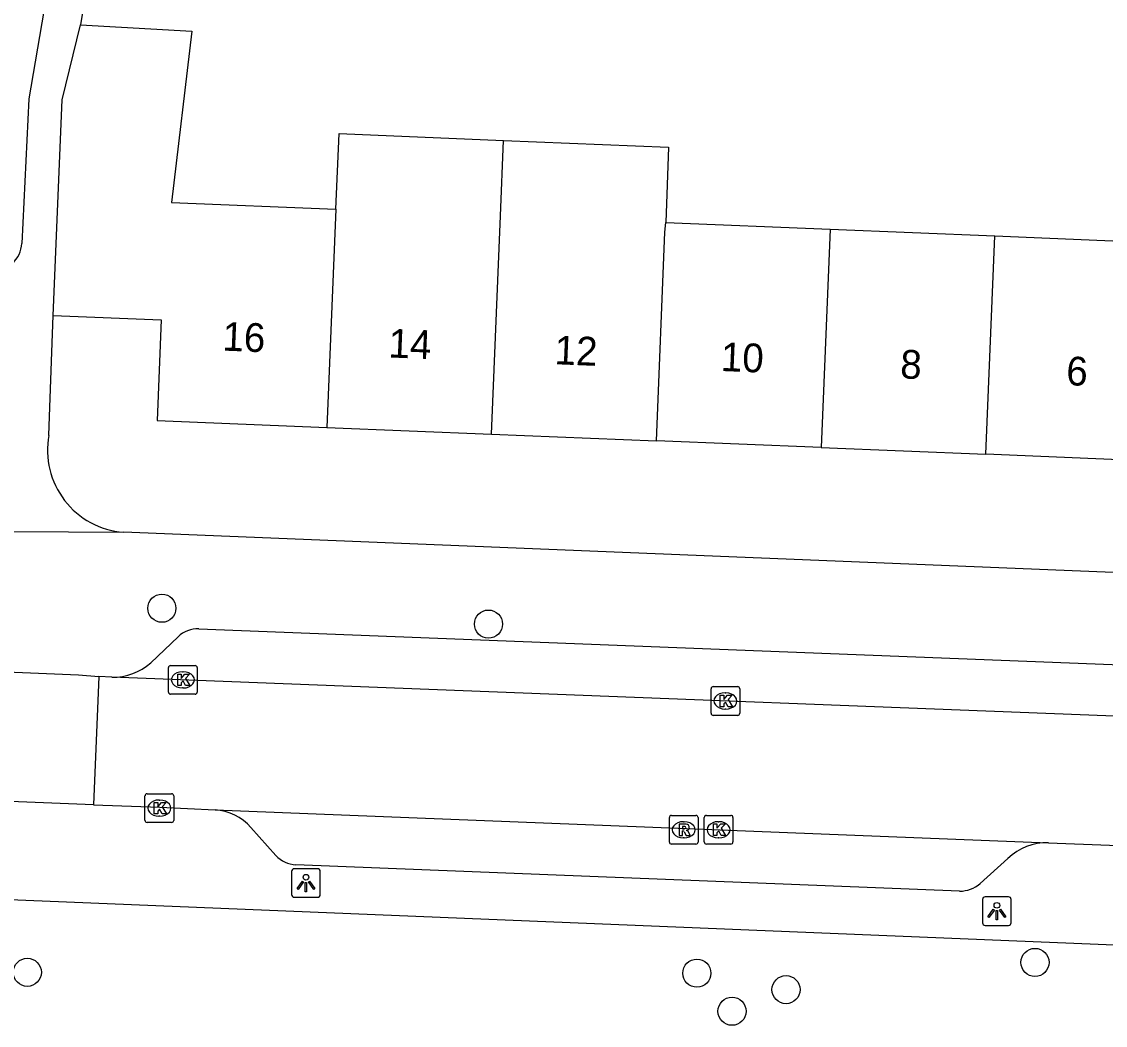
# Model space of a CAD drawing. Extents: x 159822 to 160765, y 380693 to 381634.
# Drawn here: x 160115.31 to 160153.02, y 380859.42 to 380894.34 of the extents above; entities that cross this region are included whole.
import ezdxf

# ---------------------------------------------------------------- set-up
doc = ezdxf.new("R2010")
doc.units = 0
for name, color, linetype in [('IMGEO_Boom', 7, 'Continuous'), ('IMGEO_Kolk', 7, 'Continuous'), ('IMGEO_Lichtpunt', 7, 'Continuous'), ('IMGEO_Muur', 7, 'Continuous'), ('IMGEO_Pand', 7, 'Continuous'), ('IMGEO_Pand_nummerreeks', 7, 'Continuous'), ('IMGEO_Rijbaan_lokaal_open', 7, 'Continuous'), ('IMGEO_Rioolput', 7, 'Continuous'), ('IMGEO_Voetpad_open', 7, 'Continuous')]:
    doc.layers.add(name, color=color, linetype=linetype)

msp = doc.modelspace()

# ---------------------------------------------------------------- linework, layer by layer
at = {"layer": 'IMGEO_Boom'}
for centre in [(160120.189, 380873.93), (160131.553, 380873.379), (160150.568, 380861.607), (160115.507, 380861.264), (160138.803, 380861.233), (160141.906, 380860.66), (160140.028, 380859.908)]:
    msp.add_circle(centre, 0.489, dxfattribs=at)
at = {"layer": 'IMGEO_Kolk'}
for p, q in [((160120.418, 380871.011), (160120.418, 380871.863)), ((160120.493, 380871.937), (160121.345, 380871.937)), ((160121.419, 380871.863), (160121.419, 380871.011)), ((160120.906, 380871.717), (160120.931, 380871.717)), ((160120.929, 380871.157), (160120.904, 380871.157)), ((160139.297, 380870.278), (160139.297, 380871.13)), ((160139.372, 380871.204), (160140.224, 380871.204)), ((160140.298, 380871.13), (160140.298, 380870.278)), ((160121.345, 380870.937), (160120.493, 380870.937)), ((160139.785, 380870.984), (160139.81, 380870.984)), ((160139.808, 380870.424), (160139.783, 380870.424)), ((160140.224, 380870.204), (160139.372, 380870.204)), ((160119.602, 380866.551), (160119.602, 380867.403)), ((160119.677, 380867.477), (160120.529, 380867.477)), ((160120.603, 380867.403), (160120.603, 380866.551)), ((160120.09, 380867.257), (160120.115, 380867.257)), ((160120.113, 380866.697), (160120.088, 380866.697)), ((160139.059, 380865.798), (160139.059, 380866.65)), ((160139.134, 380866.724), (160139.986, 380866.724)), ((160140.06, 380866.65), (160140.06, 380865.798)), ((160120.529, 380866.477), (160119.677, 380866.477)), ((160139.547, 380866.504), (160139.572, 380866.504)), ((160139.57, 380865.944), (160139.545, 380865.944)), ((160139.986, 380865.724), (160139.134, 380865.724))]:
    msp.add_line(p, q, dxfattribs=at)
for points in [[(160120.418, 380871.011), (160120.418, 380871.863)], [(160120.493, 380871.937), (160121.345, 380871.937)], [(160121.419, 380871.863), (160121.419, 380871.011)], [(160120.739, 380871.637), (160120.862, 380871.637), (160120.862, 380871.486), (160120.992, 380871.637), (160121.156, 380871.637), (160121.01, 380871.486), (160121.163, 380871.237), (160121.011, 380871.237), (160120.926, 380871.401), (160120.862, 380871.334), (160120.862, 380871.237), (160120.739, 380871.237), (160120.739, 380871.637)], [(160139.297, 380870.278), (160139.297, 380871.13)], [(160139.372, 380871.204), (160140.224, 380871.204)], [(160140.298, 380871.13), (160140.298, 380870.278)], [(160121.345, 380870.937), (160120.493, 380870.937)], [(160139.618, 380870.904), (160139.741, 380870.904), (160139.741, 380870.753), (160139.871, 380870.904), (160140.035, 380870.904), (160139.889, 380870.753), (160140.042, 380870.504), (160139.89, 380870.504), (160139.805, 380870.668), (160139.741, 380870.601), (160139.741, 380870.504), (160139.618, 380870.504), (160139.618, 380870.904)], [(160140.224, 380870.204), (160139.372, 380870.204)], [(160119.602, 380866.551), (160119.602, 380867.403)], [(160119.677, 380867.477), (160120.529, 380867.477)], [(160120.603, 380867.403), (160120.603, 380866.551)], [(160119.923, 380867.177), (160120.046, 380867.177), (160120.046, 380867.026), (160120.176, 380867.177), (160120.34, 380867.177), (160120.194, 380867.026), (160120.347, 380866.777), (160120.195, 380866.777), (160120.11, 380866.941), (160120.046, 380866.874), (160120.046, 380866.777), (160119.923, 380866.777), (160119.923, 380867.177)], [(160139.059, 380865.798), (160139.059, 380866.65)], [(160139.134, 380866.724), (160139.986, 380866.724)], [(160140.06, 380866.65), (160140.06, 380865.798)], [(160120.529, 380866.477), (160119.677, 380866.477)], [(160139.38, 380866.424), (160139.503, 380866.424), (160139.503, 380866.273), (160139.633, 380866.424), (160139.797, 380866.424), (160139.651, 380866.273), (160139.804, 380866.024), (160139.652, 380866.024), (160139.567, 380866.188), (160139.503, 380866.121), (160139.503, 380866.024), (160139.38, 380866.024), (160139.38, 380866.424)], [(160139.986, 380865.724), (160139.134, 380865.724)]]:
    msp.add_lwpolyline(points, dxfattribs=at)
for centre, start, end in [((160120.495, 380871.861), 91.552, 178.448), ((160120.495, 380871.861), 91.552, 178.448), ((160121.343, 380871.861), 1.552, 88.448), ((160121.343, 380871.861), 1.552, 88.448), ((160139.374, 380871.128), 91.552, 178.448), ((160139.374, 380871.128), 91.552, 178.448), ((160140.222, 380871.128), 1.552, 88.448), ((160140.222, 380871.128), 1.552, 88.448), ((160120.495, 380871.013), 181.552, 268.448), ((160120.495, 380871.013), 181.552, 268.448), ((160121.343, 380871.013), 271.552, 358.448), ((160121.343, 380871.013), 271.552, 358.448), ((160139.374, 380870.28), 181.552, 268.448), ((160139.374, 380870.28), 181.552, 268.448), ((160140.222, 380870.28), 271.552, 358.448), ((160140.222, 380870.28), 271.552, 358.448), ((160119.679, 380867.401), 91.552, 178.448), ((160119.679, 380867.401), 91.552, 178.448), ((160120.527, 380867.401), 1.552, 88.448), ((160120.527, 380867.401), 1.552, 88.448), ((160119.679, 380866.553), 181.552, 268.448), ((160119.679, 380866.553), 181.552, 268.448), ((160120.527, 380866.553), 271.552, 358.448), ((160120.527, 380866.553), 271.552, 358.448), ((160139.136, 380866.648), 91.552, 178.448), ((160139.136, 380866.648), 91.552, 178.448), ((160139.984, 380866.648), 1.552, 88.448), ((160139.984, 380866.648), 1.552, 88.448), ((160139.136, 380865.8), 181.552, 268.448), ((160139.136, 380865.8), 181.552, 268.448), ((160139.984, 380865.8), 271.552, 358.448), ((160139.984, 380865.8), 271.552, 358.448)]:
    msp.add_arc(centre, 0.0765, start, end, dxfattribs=at)
for centre, major_axis, ratio, start_param, end_param in [((160120.905, 380871.437), (-0.387, 0.002), 0.722429, 4.712389, 7.853982), ((160120.93, 380871.437), (-0.39, 0.002), 0.717154, 1.570796, 4.712389), ((160139.784, 380870.704), (-0.387, 0.002), 0.722429, 4.712389, 7.853982), ((160139.809, 380870.704), (-0.39, 0.002), 0.717154, 1.570796, 4.712389), ((160120.089, 380866.977), (-0.387, 0.002), 0.722429, 4.712389, 7.853982), ((160120.114, 380866.977), (-0.39, 0.002), 0.717154, 1.570796, 4.712389), ((160139.546, 380866.224), (-0.387, 0.002), 0.722429, 4.712389, 7.853982), ((160139.571, 380866.224), (-0.39, 0.002), 0.717154, 1.570796, 4.712389)]:
    msp.add_ellipse(centre, major_axis=major_axis, ratio=ratio, start_param=start_param, end_param=end_param, dxfattribs=at)
at = {"layer": 'IMGEO_Lichtpunt'}
for p, q in [((160124.704, 380864.774), (160124.704, 380863.967)), ((160124.704, 380864.774), (160124.704, 380863.967)), ((160125.606, 380864.869), (160124.798, 380864.869)), ((160125.606, 380864.869), (160124.798, 380864.869)), ((160125.7, 380863.967), (160125.7, 380864.774)), ((160125.7, 380863.967), (160125.7, 380864.774)), ((160124.798, 380863.873), (160125.606, 380863.873)), ((160124.798, 380863.873), (160125.606, 380863.873)), ((160148.743, 380863.795), (160148.743, 380862.988)), ((160148.743, 380863.795), (160148.743, 380862.988)), ((160149.645, 380863.89), (160148.837, 380863.89)), ((160149.645, 380863.89), (160148.837, 380863.89)), ((160149.739, 380862.988), (160149.739, 380863.795)), ((160149.739, 380862.988), (160149.739, 380863.795)), ((160148.837, 380862.894), (160149.645, 380862.894)), ((160148.837, 380862.894), (160149.645, 380862.894))]:
    msp.add_line(p, q, dxfattribs=at)
for points in [[(160125.078, 380864.438), (160125.117, 380864.41), (160124.929, 380864.148), (160124.891, 380864.175), (160125.078, 380864.438)], [(160125.18, 380864.39), (160125.227, 380864.39), (160125.227, 380864.068), (160125.18, 380864.068), (160125.18, 380864.39)], [(160125.29, 380864.41), (160125.328, 380864.437), (160125.515, 380864.175), (160125.476, 380864.147), (160125.29, 380864.41)], [(160149.117, 380863.459), (160149.156, 380863.431), (160148.968, 380863.169), (160148.93, 380863.196), (160149.117, 380863.459)], [(160149.219, 380863.411), (160149.266, 380863.411), (160149.266, 380863.089), (160149.219, 380863.089), (160149.219, 380863.411)], [(160149.329, 380863.431), (160149.367, 380863.458), (160149.554, 380863.196), (160149.515, 380863.168), (160149.329, 380863.431)]]:
    msp.add_lwpolyline(points, dxfattribs=at)
for centre in [(160125.203, 380864.572), (160149.242, 380863.593)]:
    msp.add_circle(centre, 0.0994, dxfattribs=at)
for centre, start, end in [((160124.798, 380864.774), 90, 180), ((160124.798, 380864.774), 90, 180), ((160125.606, 380864.774), 0, 90), ((160125.606, 380864.774), 0, 90), ((160124.798, 380863.967), 180, 270), ((160124.798, 380863.967), 180, 270), ((160125.606, 380863.967), 270, 0), ((160125.606, 380863.967), 270, 360), ((160148.837, 380863.795), 90, 180), ((160148.837, 380863.795), 90, 180), ((160149.645, 380863.795), 0, 90), ((160149.645, 380863.795), 0, 90), ((160148.837, 380862.988), 180, 270), ((160148.837, 380862.988), 180, 270), ((160149.645, 380862.988), 270, 0), ((160149.645, 380862.988), 270, 360)]:
    msp.add_arc(centre, 0.0946, start, end, dxfattribs=at)
at = {"layer": 'IMGEO_Muur'}
msp.add_lwpolyline([(160118.101, 380898.814), (160117.362, 380894.233)], dxfattribs=at)
at = {"layer": 'IMGEO_Pand'}
for points in [[(160116.411, 380884.119), (160116.721, 380891.622), (160117.362, 380894.233)], [(160117.362, 380894.233), (160121.236, 380894.01), (160120.519, 380888.053), (160126.247, 380887.819)], [(160126.247, 380887.819), (160126.357, 380890.443), (160132.079, 380890.209)], [(160131.662, 380879.99), (160131.972, 380887.585), (160132.079, 380890.209)], [(160132.079, 380890.209), (160137.813, 380889.975), (160137.722, 380887.351)], [(160126.247, 380887.819), (160125.929, 380880.224)], [(160137.395, 380879.755), (160137.692, 380887.01), (160137.722, 380887.351)], [(160137.722, 380887.351), (160143.439, 380887.117)], [(160143.439, 380887.117), (160143.128, 380879.521)], [(160143.439, 380887.117), (160149.174, 380886.883)], [(160148.862, 380879.287), (160149.174, 380886.883)], [(160149.174, 380886.883), (160154.918, 380886.649)], [(160116.411, 380884.119), (160120.167, 380883.963), (160120.023, 380880.465), (160125.929, 380880.224)], [(160125.929, 380880.224), (160131.662, 380879.99)], [(160131.662, 380879.99), (160137.395, 380879.755)], [(160143.128, 380879.521), (160137.395, 380879.755)], [(160143.128, 380879.521), (160148.862, 380879.287)], [(160154.595, 380879.053), (160148.862, 380879.287)]]:
    msp.add_lwpolyline(points, dxfattribs=at)
at = {"layer": 'IMGEO_Rijbaan_lokaal_open'}
for points in [[(160111.159, 380871.87), (160117.285, 380871.609), (160117.994, 380871.561)], [(160117.994, 380871.561), (160117.81, 380867.096)], [(160118.45, 380871.532), (160117.994, 380871.561)], [(160164.369, 380869.749), (160118.45, 380871.532)], [(160117.81, 380867.096), (160103.608, 380867.658)], [(160117.81, 380867.096), (160120.123, 380867.005), (160122.045, 380866.92)], [(160122.045, 380866.92), (160151.04, 380865.77)], [(160151.04, 380865.77), (160165.892, 380865.196), (160166.661, 380865.312)]]:
    msp.add_lwpolyline(points, dxfattribs=at)
at = {"layer": 'IMGEO_Rioolput'}
for p, q in [((160137.846, 380865.797), (160137.846, 380866.649)), ((160137.921, 380866.723), (160138.773, 380866.723)), ((160138.847, 380866.649), (160138.847, 380865.797)), ((160138.334, 380866.503), (160138.359, 380866.503)), ((160138.357, 380865.943), (160138.332, 380865.943)), ((160138.773, 380865.723), (160137.921, 380865.723))]:
    msp.add_line(p, q, dxfattribs=at)
for points in [[(160137.846, 380865.797), (160137.846, 380866.649)], [(160137.921, 380866.723), (160138.773, 380866.723)], [(160138.847, 380866.649), (160138.847, 380865.797)], [(160138.435, 380866.421), (160138.183, 380866.423), (160138.183, 380866.023)], [(160138.183, 380866.023), (160138.307, 380866.023), (160138.307, 380866.185), (160138.318, 380866.185)], [(160138.361, 380866.342), (160138.307, 380866.342), (160138.307, 380866.261)], [(160138.307, 380866.261), (160138.359, 380866.261)], [(160138.365, 380866.156), (160138.436, 380866.023), (160138.576, 380866.023), (160138.511, 380866.149)], [(160138.773, 380865.723), (160137.921, 380865.723)]]:
    msp.add_lwpolyline(points, dxfattribs=at)
for centre, radius, start, end in [((160137.923, 380866.647), 0.0765, 91.552, 178.448), ((160137.923, 380866.647), 0.0765, 91.552, 178.448), ((160138.771, 380866.647), 0.0765, 1.552, 88.448), ((160138.771, 380866.647), 0.0765, 1.552, 88.448), ((160138.317, 380866.132), 0.0533, 26.0293, 88.6989), ((160138.343, 380866.45), 0.19, 274.7715, 282.9687), ((160138.367, 380866.246), 0.0964, 77.0061, 93.1865), ((160138.381, 380866.303), 0.0378, 276.6634, 79.6772), ((160138.434, 380866.311), 0.109, 350.3612, 89.416), ((160138.432, 380866.311), 0.112, 277.5842, 350.9817), ((160138.416, 380866.096), 0.108, 29.5134, 73.7905), ((160137.923, 380865.799), 0.0765, 181.552, 268.448), ((160137.923, 380865.799), 0.0765, 181.552, 268.448), ((160138.771, 380865.799), 0.0765, 271.552, 358.448), ((160138.771, 380865.799), 0.0765, 271.552, 358.448)]:
    msp.add_arc(centre, radius, start, end, dxfattribs=at)
for centre, major_axis, ratio, start_param, end_param in [((160138.333, 380866.223), (-0.387, 0.002), 0.722429, 4.712389, 7.853982), ((160138.358, 380866.223), (-0.39, 0.002), 0.717154, 1.570796, 4.712389)]:
    msp.add_ellipse(centre, major_axis=major_axis, ratio=ratio, start_param=start_param, end_param=end_param, dxfattribs=at)
at = {"layer": 'IMGEO_Voetpad_open'}
for points in [[(160118.292, 380907.642), (160118.261, 380907.458), (160115.561, 380891.657), (160115.311, 380886.625)], [(160118.101, 380898.814), (160117.362, 380894.233)], [(160116.256, 380879.946), (160116.28, 380880.602), (160116.411, 380884.119)], [(160113.106, 380876.611), (160118.85, 380876.572)], [(160163.251, 380874.767), (160118.85, 380876.572)], [(160121.476, 380873.219), (160161.575, 380871.646)], [(160119.804, 380872.032), (160120.752, 380872.934)], [(160169.444, 380861.549), (160005.773, 380868.257), (159996.586, 380868.629), (159996.603, 380869.516), (159993.946, 380869.644), (159993.895, 380868.739), (159985.923, 380869.026)], [(160124.157, 380865.327), (160123.289, 380866.301)], [(160149.625, 380865.225), (160148.664, 380864.351)], [(160147.946, 380864.087), (160124.851, 380865.007)]]:
    msp.add_lwpolyline(points, dxfattribs=at)
for centre, radius, start, end in [((160114.41, 380886.632), 0.901, 308.7417, 359.5862), ((160119.081, 380879.434), 2.871, 169.7318, 265.3758), ((160121.455, 380872.211), 1.008, 88.7888, 134.185), ((160118.489, 380873.51), 1.978, 268.8692, 311.6668), ((160121.89, 380865.049), 1.878, 41.8278, 85.2634), ((160150.976, 380863.826), 1.945, 88.1215, 134.0078), ((160124.903, 380866.032), 1.026, 223.3761, 267.1155), ((160147.947, 380865.191), 1.104, 269.9248, 310.451)]:
    msp.add_arc(centre, radius, start, end, dxfattribs=at)

# ---------------------------------------------------------------- texts
at = {"layer": 'IMGEO_Pand_nummerreeks'}
for s, rotation, p in [('16', 357.6607, (160122.281, 380882.896)), ('14', 357.6623, (160128.062, 380882.658)), ('12', 357.6623, (160133.839, 380882.422)), ('10', 357.6607, (160139.625, 380882.186)), ('8', 357.6607, (160145.866, 380881.931)), ('6', 357.6607, (160151.642, 380881.696))]:
    msp.add_text(s, height=1, rotation=rotation, dxfattribs=at).set_placement(p)

doc.saveas('drawing.dxf')
